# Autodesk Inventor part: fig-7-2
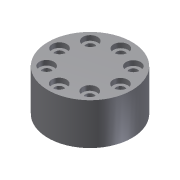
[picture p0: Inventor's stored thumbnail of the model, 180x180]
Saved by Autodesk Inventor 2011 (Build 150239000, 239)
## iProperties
Created: 2004-05
Part Number: fig-7-2
Document SubType Name: Modeling
Designer: CADCIM Technologies
Manufacturer: Standard
Standards Organization: Custom
Density: 1 g/cm^3
Author: CADCIM Technologies
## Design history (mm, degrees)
sketch "Sketch1"
  geometry: C1 r 17.175 at (0, 0)
  constraints: 1 centre point
extrude "Extrusion1" new body sketch "Sketch1" distance "d0" = 17; taper "d1" = 0 deg
sketch "Sketch2"
  geometry: 1 further point
hole "Hole1" sketch "Sketch2" at (12.571, -0.074) diameter "d2" = 3.5; stored, may be unused: countersink angle "d6" = 90 deg, drill point angle "d8" = 118 deg; dims "d3" = 6, "d4" = 6, "d5" = 2, "d7" = 8
pattern_circular "Circular Pattern1" dims angle "d11" = 360 deg
body "Solid1"
